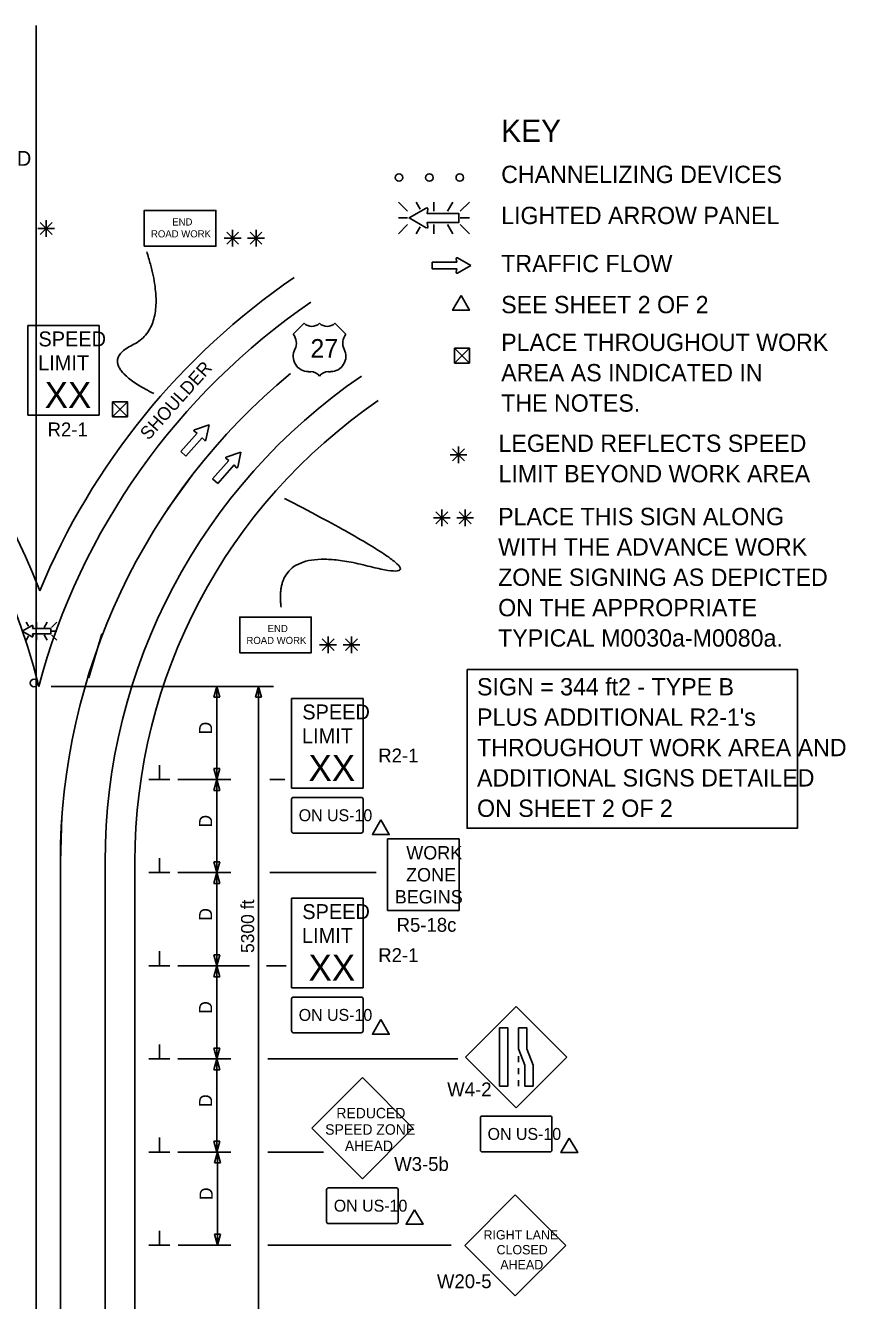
# Model space of a CAD drawing. Extents: x 16751 to 18479, y 5718 to 6974.
# Drawn here: x 16999 to 17439, y 6290 to 6974 of the extents above; entities that cross this region are included whole.
import ezdxf

# ---------------------------------------------------------------- set-up
doc = ezdxf.new("R2010")
doc.units = 0
for name, color, linetype in [('ALI_LEGAL_EX', 7, 'Continuous'), ('MT_SCRATCH_LEVEL_E', 7, 'Continuous'), ('PAVT_EDGE_EX', 7, 'Continuous'), ('TRAFFIC_SIGNS_PR', 7, 'Continuous'), ('TYPICAL_EX', 7, 'Continuous'), ('TYPICAL_TEXT_DIMEN_EX', 7, 'Continuous'), ('TYPICAL_TEXT_DIMEN_PR', 7, 'Continuous')]:
    doc.layers.add(name, color=color, linetype=linetype)

msp = doc.modelspace()

# ---------------------------------------------------------------- linework, layer by layer
at = {"layer": 'ALI_LEGAL_EX'}
for p, q in [((17004.68, 6974.12), (17004.68, 6155.98)), ((17004.68, 6877.04), (17004.68, 6013.12)), ((17039.84, 6647.53), (17032.85, 6623.88)), ((17017.65, 6024.8), (17017.65, 6525.15))]:
    msp.add_line(p, q, dxfattribs=at)
for points in [[(17004.68, 6949.12), (17004.68, 6974.12)], [(17075.14, 6714.42), (17089.89, 6734.61)], [(17017.7, 6524.8), (17017.65, 6525.15), (17018.48, 6549.78)], [(17017.65, 6424.8), (17017.65, 6449.8)], [(17017.7, 6324.8), (17017.7, 6349.8)]]:
    msp.add_lwpolyline(points, dxfattribs=at)
msp.add_arc((17357.65, 6525.15), 340, 129.56655, 180, dxfattribs=at)
at = {"layer": 'MT_SCRATCH_LEVEL_E'}
for p, q in [((17230.34, 6847.14), (17217.09, 6847.14)), ((17217.09, 6847.14), (17217.09, 6843.4)), ((17230.03, 6848.91), (17230.34, 6847.14)), ((17237.95, 6845.28), (17230.71, 6849.4)), ((17230.71, 6841.14), (17237.95, 6845.28)), ((17217.09, 6843.4), (17230.34, 6843.4)), ((17230.34, 6843.4), (17230.03, 6841.62)), ((17089.5, 6756.28), (17091.04, 6755.33)), ((17097.48, 6759.79), (17089.6, 6757.11)), ((17095.77, 6751.62), (17097.48, 6759.79)), ((17091.04, 6755.33), (17082.24, 6745.42)), ((17085.03, 6742.93), (17093.84, 6752.84)), ((17093.84, 6752.84), (17094.96, 6751.43)), ((17082.24, 6745.42), (17085.03, 6742.93)), ((17114.56, 6745.13), (17106.68, 6742.45)), ((17112.85, 6736.96), (17114.56, 6745.13)), ((17108.12, 6740.67), (17099.32, 6730.76)), ((17102.12, 6728.28), (17110.92, 6738.19)), ((17106.59, 6741.62), (17108.12, 6740.67)), ((17110.92, 6738.19), (17112.04, 6736.77)), ((17099.32, 6730.76), (17102.12, 6728.28))]:
    msp.add_line(p, q, dxfattribs=at)
for centre, start, end in [((17230.49, 6848.99), 60.42484, 189.96381), ((17230.49, 6841.55), 170.03619, 299.77312), ((17089.75, 6756.67), 108.80279, 238.34176), ((17095.31, 6751.73), 218.41415, 348.15107), ((17106.84, 6742.01), 108.80279, 238.34176), ((17112.4, 6737.07), 218.41415, 348.15107)]:
    msp.add_arc(centre, 0.463, start, end, dxfattribs=at)
at = {"layer": 'PAVT_EDGE_EX'}
for p, q in [((17041.65, 6525.15), (17041.65, 6186.91)), ((17057.65, 6525.15), (17057.65, 6186.91))]:
    msp.add_line(p, q, dxfattribs=at)
for centre, radius, start, end in [((16629.65, 6525.15), 404, 21.09612, 66.09058), ((16629.65, 6525.15), 388, 14.04823, 66.09058), ((17357.65, 6525.15), 380, 124.38118, 157.50106), ((17357.65, 6525.15), 364, 124.38118, 165.0045), ((17357.65, 6525.15), 316, 124.38117, 180), ((17357.65, 6525.15), 300, 124.38117, 180), ((17357.65, 6525.15), 300, 180, 180.00000277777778)]:
    msp.add_arc(centre, radius, start, end, dxfattribs=at)
at = {"layer": 'TRAFFIC_SIGNS_PR'}
for p, q in [((17199.02, 6879.29), (17203.95, 6874.36)), ((17210.78, 6875.47), (17208.57, 6879.3)), ((17218.1, 6874.36), (17218.1, 6879.3)), ((17225.34, 6874.36), (17228.19, 6879.3)), ((17232.25, 6874.36), (17237.19, 6879.3)), ((17203.95, 6870.8), (17199.02, 6870.8)), ((17199.02, 6862.32), (17203.95, 6867.25)), ((17208.53, 6862.31), (17210.64, 6865.98)), ((17218.1, 6867.25), (17218.1, 6862.31)), ((17228.23, 6862.31), (17225.38, 6867.25)), ((17232.25, 6870.8), (17237.19, 6870.8)), ((17232.25, 6867.25), (17237.19, 6862.31)), ((17000.14, 6813), (17038.54, 6813)), ((17000.14, 6765), (17000.14, 6813)), ((17038.54, 6765), (17038.54, 6813)), ((17000.14, 6765), (17038.54, 6765)), ((17000.64, 6651.64), (16999.38, 6653.82)), ((17004.82, 6651.01), (17004.82, 6653.82)), ((17008.96, 6651.01), (17010.59, 6653.82)), ((17012.91, 6651.01), (17015.73, 6653.83)), ((17004.82, 6646.94), (17004.82, 6644.12)), ((17010.61, 6644.12), (17008.98, 6646.94)), ((17012.91, 6648.97), (17015.73, 6648.97)), ((17012.91, 6646.94), (17015.73, 6644.12)), ((16999.35, 6644.12), (17000.56, 6646.21)), ((17141.7, 6612.74), (17180.1, 6612.74)), ((17141.7, 6564.74), (17141.7, 6612.74)), ((17180.1, 6564.74), (17180.1, 6612.74)), ((17141.7, 6564.74), (17180.1, 6564.74)), ((17141.7, 6558.74), (17141.7, 6541.54)), ((17142.7, 6559.74), (17179.1, 6559.74)), ((17180.1, 6558.74), (17180.1, 6541.54)), ((17142.7, 6540.54), (17179.1, 6540.54)), ((17193.28, 6499.02), (17193.28, 6537.42)), ((17193.28, 6537.42), (17231.68, 6537.42)), ((17231.68, 6499.02), (17231.68, 6537.42)), ((17141.7, 6505.55), (17180.1, 6505.55)), ((17141.7, 6457.55), (17141.7, 6505.55)), ((17180.1, 6457.55), (17180.1, 6505.55)), ((17193.28, 6499.02), (17231.68, 6499.02)), ((17141.7, 6457.55), (17180.1, 6457.55)), ((17141.7, 6451.55), (17141.7, 6434.35)), ((17142.7, 6452.55), (17179.1, 6452.55)), ((17180.1, 6451.55), (17180.1, 6434.35)), ((17262.25, 6447.4), (17235.1, 6420.25)), ((17289.4, 6420.25), (17262.25, 6447.4)), ((17142.7, 6433.35), (17179.1, 6433.35)), ((17263.49, 6420.74), (17263.49, 6417.54)), ((17235.1, 6420.25), (17262.25, 6393.1)), ((17262.25, 6393.1), (17289.4, 6420.25)), ((17263.49, 6414.34), (17263.49, 6411.14)), ((17179.71, 6409.29), (17152.55, 6382.13)), ((17206.86, 6382.13), (17179.71, 6409.29)), ((17263.49, 6407.94), (17263.49, 6404.74)), ((17243.05, 6387.65), (17243.05, 6370.45)), ((17244.05, 6388.65), (17280.45, 6388.65)), ((17281.45, 6387.65), (17281.45, 6370.45)), ((17152.55, 6382.13), (17179.71, 6354.98)), ((17179.71, 6354.98), (17206.86, 6382.13)), ((17244.05, 6369.45), (17280.45, 6369.45)), ((17160.53, 6349.13), (17160.53, 6331.93)), ((17161.53, 6350.13), (17197.93, 6350.13)), ((17198.93, 6349.13), (17198.93, 6331.93)), ((17261.76, 6346.39), (17234.61, 6319.24)), ((17288.91, 6319.24), (17261.76, 6346.39)), ((17161.53, 6330.93), (17197.93, 6330.93)), ((17234.61, 6319.24), (17261.76, 6292.09)), ((17261.76, 6292.09), (17288.91, 6319.24))]:
    msp.add_line(p, q, dxfattribs=at)
for points in [[(17062.69, 6855.62), (17101.09, 6855.62), (17101.09, 6874.82), (17062.69, 6874.82)], [(17113.9, 6637.34), (17152.3, 6637.34), (17152.3, 6656.54), (17113.9, 6656.54)], [(17253.36, 6435.99), (17253.36, 6404.74), (17257.85, 6404.74), (17257.85, 6435.99)], [(17263.49, 6435.99), (17263.49, 6424.8), (17266.84, 6415.92), (17266.84, 6404.74), (17271.33, 6404.74), (17271.33, 6415.92), (17267.99, 6424.8), (17267.99, 6435.99)]]:
    msp.add_lwpolyline(points, close=True, dxfattribs=at)
for points in [[(17214.03, 6876.08), (17204.74, 6870.8), (17214.03, 6865.48)], [(17214.9, 6866.11), (17214.5, 6868.38), (17231.52, 6868.38), (17231.52, 6873.18), (17214.5, 6873.18), (17214.91, 6875.46)], [(17002.5, 6651.99), (16997.19, 6648.97), (17002.5, 6645.93)], [(17003, 6646.29), (17002.77, 6647.59), (17012.49, 6647.59), (17012.49, 6650.33), (17002.77, 6650.33), (17003, 6651.63)]]:
    msp.add_lwpolyline(points, dxfattribs=at)
for centre in [(17199.36, 6892.49), (17215.66, 6892.49), (17231.96, 6892.49), (17003.5, 6621.15)]:
    msp.add_circle(centre, 2, dxfattribs=at)
for centre, radius, start, end in [((17214.32, 6875.56), 0.598, 350.73078, 118.89165), ((17214.32, 6866.01), 0.597, 241.48329, 9.95933), ((17002.66, 6651.69), 0.341, 350.73078, 118.89165), ((17002.66, 6646.23), 0.341, 241.48329, 9.95933), ((17142.7, 6558.74), 1, 90, 180), ((17179.1, 6558.74), 1, 0, 90), ((17142.7, 6541.54), 1, 180, 270), ((17179.1, 6541.54), 1, 270, 0), ((17142.7, 6451.55), 1, 90, 180), ((17179.1, 6451.55), 1, 0, 90), ((17142.7, 6434.35), 1, 180, 270), ((17179.1, 6434.35), 1, 270, 0), ((17244.05, 6387.65), 1, 90, 180), ((17280.45, 6387.65), 1, 0, 90), ((17244.05, 6370.45), 1, 180, 270), ((17280.45, 6370.45), 1, 270, 0), ((17161.53, 6349.13), 1, 90, 180), ((17197.93, 6349.13), 1, 0, 90), ((17161.53, 6331.93), 1, 180, 270), ((17197.93, 6331.93), 1, 270, 0)]:
    msp.add_arc(centre, radius, start, end, dxfattribs=at)
at = {"layer": 'TYPICAL_EX'}
for p, q in [((17142.58, 6808.34), (17148.47, 6814.24)), ((17170.88, 6808.34), (17164.98, 6814.24)), ((17150.83, 6788.28), (17152, 6788.28)), ((17162.63, 6788.28), (17161.45, 6788.28))]:
    msp.add_line(p, q, dxfattribs=at)
for centre, radius, start, end in [((17152.6, 6818.53), 5.96, 226.14041, 313.85958), ((17160.86, 6818.53), 5.96, 226.14042, 313.85959), ((17136.99, 6803.62), 7.31, 333.09768, 40.19361), ((17176.46, 6803.62), 7.31, 139.80639, 206.90233), ((17150.84, 6796.53), 8.24, 152.6698, 269.90132), ((17162.62, 6796.53), 8.24, 270.09868, 27.3302), ((17152.02, 6782.38), 5.91, 37.1038, 90.13853), ((17161.44, 6782.38), 5.91, 89.86147, 142.8962)]:
    msp.add_arc(centre, radius, start, end, dxfattribs=at)
at = {"layer": 'TYPICAL_TEXT_DIMEN_EX'}
msp.add_lwpolyline([(17235.92, 6628.43), (17413.13, 6628.43), (17413.13, 6543.16), (17235.92, 6543.16)], close=True, dxfattribs=at)
at = {"layer": 'TYPICAL_TEXT_DIMEN_PR'}
for p, q in [((17006.83, 6868.3), (17013.21, 6861.92)), ((17013.21, 6868.3), (17006.83, 6861.92)), ((17010.02, 6865.11), (17010.02, 6869.57)), ((17010.02, 6865.11), (17005.49, 6865.11)), ((17010.02, 6865.11), (17013.21, 6865.11)), ((17010.02, 6865.11), (17014.5, 6865.11)), ((17010.02, 6865.11), (17010.02, 6860.61)), ((17110.11, 6859.99), (17105.58, 6859.99)), ((17106.92, 6863.18), (17113.3, 6856.8)), ((17113.3, 6863.18), (17106.92, 6856.8)), ((17110.11, 6859.99), (17110.11, 6864.45)), ((17110.11, 6859.99), (17113.3, 6859.99)), ((17110.11, 6859.99), (17114.59, 6859.99)), ((17110.11, 6859.99), (17110.11, 6855.49)), ((17122.67, 6859.99), (17118.13, 6859.99)), ((17119.48, 6863.18), (17125.85, 6856.8)), ((17125.85, 6863.18), (17119.48, 6856.8)), ((17122.67, 6859.99), (17122.67, 6864.45)), ((17122.67, 6859.99), (17125.85, 6859.99)), ((17122.67, 6859.99), (17127.14, 6859.99)), ((17122.67, 6859.99), (17122.67, 6855.49)), ((17229.19, 6800.9), (17237.19, 6792.9)), ((17229.19, 6792.9), (17237.19, 6800.9)), ((17045.67, 6764.12), (17053.67, 6772.12)), ((17045.68, 6772.12), (17053.67, 6764.12)), ((17231.33, 6743.67), (17226.8, 6743.67)), ((17228.14, 6746.86), (17234.52, 6740.48)), ((17234.52, 6746.86), (17228.14, 6740.48)), ((17231.33, 6743.67), (17231.33, 6748.13)), ((17231.33, 6743.67), (17234.52, 6743.67)), ((17231.33, 6743.67), (17235.81, 6743.67)), ((17231.33, 6743.67), (17231.33, 6739.17)), ((17222.33, 6709.8), (17217.79, 6709.8)), ((17219.14, 6712.99), (17225.51, 6706.61)), ((17225.51, 6712.99), (17219.14, 6706.61)), ((17222.33, 6709.8), (17222.33, 6714.25)), ((17222.33, 6709.8), (17225.51, 6709.8)), ((17222.33, 6709.8), (17226.8, 6709.8)), ((17222.33, 6709.8), (17222.33, 6705.3)), ((17234.88, 6709.8), (17230.35, 6709.8)), ((17231.69, 6712.99), (17238.07, 6706.61)), ((17238.07, 6712.99), (17231.69, 6706.61)), ((17234.88, 6709.8), (17234.88, 6714.25)), ((17234.88, 6709.8), (17238.07, 6709.8)), ((17234.88, 6709.8), (17239.36, 6709.8)), ((17234.88, 6709.8), (17234.88, 6705.3)), ((17161.32, 6641.72), (17156.79, 6641.72)), ((17158.13, 6644.9), (17164.51, 6638.53)), ((17164.51, 6644.9), (17158.13, 6638.53)), ((17161.32, 6641.72), (17161.32, 6646.17)), ((17161.32, 6641.72), (17164.51, 6641.72)), ((17161.32, 6641.72), (17165.8, 6641.72)), ((17161.32, 6641.72), (17161.32, 6637.22)), ((17173.87, 6641.72), (17169.34, 6641.72)), ((17170.69, 6644.9), (17177.06, 6638.53)), ((17177.06, 6644.9), (17170.69, 6638.53)), ((17173.87, 6641.72), (17173.87, 6646.17)), ((17173.87, 6641.72), (17177.06, 6641.72)), ((17173.87, 6641.72), (17178.35, 6641.72)), ((17173.87, 6641.72), (17173.87, 6637.22)), ((17012.72, 6619.33), (17106.65, 6619.33)), ((17132.09, 6619.33), (17060.95, 6619.33)), ((17100.08, 6613.47), (17101.65, 6619.33)), ((17101.65, 6619.33), (17103.22, 6613.47)), ((17101.65, 6619.33), (17101.65, 6569.33)), ((17122.44, 6613.47), (17124.01, 6619.33)), ((17124.01, 6619.33), (17124.01, 6219.33)), ((17124.01, 6619.33), (17125.58, 6613.47)), ((17101.65, 6613.47), (17100.08, 6613.47)), ((17103.22, 6613.47), (17101.65, 6613.47)), ((17124.01, 6613.47), (17122.44, 6613.47)), ((17125.58, 6613.47), (17124.01, 6613.47)), ((17070.77, 6569.33), (17070.77, 6577.11)), ((17101.65, 6569.33), (17100.08, 6575.19)), ((17100.08, 6575.19), (17101.65, 6575.19)), ((17101.65, 6575.19), (17103.22, 6575.19)), ((17103.22, 6575.19), (17101.65, 6569.33)), ((17076.4, 6569.33), (17065.15, 6569.33)), ((17080.65, 6569.33), (17109.05, 6569.33)), ((17100.08, 6563.47), (17101.65, 6569.33)), ((17101.65, 6569.33), (17101.65, 6519.33)), ((17101.65, 6569.33), (17103.22, 6563.47)), ((17129.98, 6569.33), (17138.18, 6569.33)), ((17101.65, 6563.47), (17100.08, 6563.47)), ((17103.22, 6563.47), (17101.65, 6563.47)), ((17070.77, 6519.33), (17070.77, 6527.11)), ((17101.65, 6519.33), (17100.08, 6525.19)), ((17100.08, 6525.19), (17101.65, 6525.19)), ((17101.65, 6525.19), (17103.22, 6525.19)), ((17103.22, 6525.19), (17101.65, 6519.33)), ((17076.4, 6519.33), (17065.15, 6519.33)), ((17080.65, 6519.33), (17109.05, 6519.33)), ((17100.08, 6513.47), (17101.65, 6519.33)), ((17101.65, 6519.33), (17101.65, 6469.33)), ((17101.65, 6519.33), (17103.22, 6513.47)), ((17129.98, 6519.33), (17187.17, 6519.33)), ((17101.65, 6513.47), (17100.08, 6513.47)), ((17103.22, 6513.47), (17101.65, 6513.47)), ((17070.77, 6469.33), (17070.77, 6477.11)), ((17076.4, 6469.33), (17065.15, 6469.33)), ((17080.65, 6469.33), (17119.21, 6469.33)), ((17101.65, 6469.33), (17100.08, 6475.19)), ((17100.08, 6475.19), (17101.65, 6475.19)), ((17100.08, 6463.47), (17101.65, 6469.33)), ((17101.65, 6475.19), (17103.22, 6475.19)), ((17103.22, 6475.19), (17101.65, 6469.33)), ((17101.65, 6469.33), (17101.65, 6419.33)), ((17101.65, 6469.33), (17103.22, 6463.47)), ((17128.28, 6469.33), (17138.75, 6469.33)), ((17101.65, 6463.47), (17100.08, 6463.47)), ((17103.22, 6463.47), (17101.65, 6463.47)), ((17070.77, 6419.33), (17070.77, 6427.11)), ((17101.65, 6419.33), (17100.08, 6425.19)), ((17100.08, 6425.19), (17101.65, 6425.19)), ((17101.65, 6425.19), (17103.22, 6425.19)), ((17103.22, 6425.19), (17101.65, 6419.33)), ((17076.4, 6419.33), (17065.15, 6419.33)), ((17080.65, 6419.33), (17109.05, 6419.33)), ((17100.08, 6413.47), (17101.65, 6419.33)), ((17101.65, 6419.33), (17101.65, 6369.33)), ((17101.65, 6419.33), (17103.22, 6413.47)), ((17129, 6419.33), (17230.93, 6419.33)), ((17101.65, 6413.47), (17100.08, 6413.47)), ((17103.22, 6413.47), (17101.65, 6413.47)), ((17070.77, 6369.33), (17070.77, 6377.11)), ((17101.65, 6369.33), (17100.08, 6375.19)), ((17100.08, 6375.19), (17101.65, 6375.19)), ((17101.65, 6375.19), (17103.22, 6375.19)), ((17103.22, 6375.19), (17101.65, 6369.33)), ((17076.4, 6369.33), (17065.15, 6369.33)), ((17080.65, 6369.33), (17109.05, 6369.33)), ((17100.36, 6363.47), (17101.93, 6369.33)), ((17101.93, 6369.33), (17101.93, 6319.33)), ((17101.93, 6369.33), (17103.51, 6363.47)), ((17158.84, 6369.33), (17129, 6369.33)), ((17101.93, 6363.47), (17100.36, 6363.47)), ((17103.51, 6363.47), (17101.93, 6363.47)), ((17070.77, 6319.33), (17070.77, 6327.11)), ((17101.93, 6319.33), (17100.36, 6325.19)), ((17100.36, 6325.19), (17101.93, 6325.19)), ((17101.93, 6325.19), (17103.51, 6325.19)), ((17103.51, 6325.19), (17101.93, 6319.33)), ((17076.4, 6319.33), (17065.15, 6319.33)), ((17080.93, 6319.33), (17109.05, 6319.33)), ((17129, 6319.33), (17227.33, 6319.33))]:
    msp.add_line(p, q, dxfattribs=at)
for points in [[(17232.66, 6829.11), (17228.14, 6821.28), (17237.19, 6821.28)], [(17229.19, 6800.9), (17229.19, 6792.9), (17237.19, 6792.9), (17237.19, 6800.9)], [(17045.68, 6772.12), (17045.67, 6764.12), (17053.67, 6764.12), (17053.67, 6772.12)], [(17189.65, 6547.6), (17185.12, 6539.77), (17194.17, 6539.77)], [(17189.65, 6440.41), (17185.12, 6432.58), (17194.17, 6432.58)], [(17290.75, 6376.83), (17286.23, 6369), (17295.28, 6369)], [(17207.73, 6338.38), (17203.21, 6330.55), (17212.26, 6330.55)]]:
    msp.add_lwpolyline(points, close=True, dxfattribs=at)
for points in [[(17067.74, 6776.56), (17035.79, 6792.58), (17076.97, 6812.63), (17064.02, 6852.67)], [(17138.01, 6720.2), (17233.21, 6670.88), (17131.63, 6697.14), (17136.1, 6661.91)]]:
    msp.add_open_spline(points, degree=2, dxfattribs=at)

# ---------------------------------------------------------------- texts
at = {"layer": 'TRAFFIC_SIGNS_PR'}
for s, height, p in [('SPEED', 8, (16965.8, 6898.79)), ('END', 3.831, (17077.69, 6866.75)), ('ROAD WORK', 3.831, (17066.3, 6860.36)), ('SPEED', 8, (17005.91, 6801.86)), ('PLACE THROUGHOUT WORK', 9.3, (17254.2, 6799.39)), ('LIMIT', 8, (17005.75, 6789.06)), ('AREA AS INDICATED IN', 9.3, (17254.2, 6783.09)), ('XX', 14.031, (17009.25, 6768.76)), ('THE NOTES.', 9.3, (17254.2, 6766.79)), ('R2-1', 7.44, (17010.82, 6753.56)), ('PLACE THIS SIGN ALONG', 9.3, (17252.56, 6705.87)), ('WITH THE ADVANCE WORK', 9.3, (17252.56, 6689.57)), ('ZONE SIGNING AS DEPICTED', 9.3, (17252.56, 6673.27)), ('ON THE APPROPRIATE', 9.3, (17252.56, 6656.97)), ('END', 3.831, (17128.9, 6648.47)), ('TYPICAL M0030a-M0080a.', 9.3, (17252.56, 6640.67)), ('ROAD WORK', 3.831, (17117.5, 6642.09)), ('SPEED', 8, (17147.47, 6601.6)), ('LIMIT', 8, (17147.3, 6588.8)), ('R2-1', 7.44, (17188.24, 6578.52)), ('XX', 14.031, (17150.81, 6568.5)), ('ON US-10', 6.4, (17145.54, 6546.94)), ('WORK', 7.217, (17203.28, 6526.39)), ('ZONE', 7.217, (17203.16, 6514.58)), ('BEGINS', 7.217, (17197.09, 6502.77)), ('SPEED', 8, (17147.47, 6494.41)), ('LIMIT', 8, (17147.3, 6481.61)), ('R5-18c', 7.44, (17198.09, 6487.59)), ('XX', 14.031, (17150.81, 6461.31)), ('R2-1', 7.44, (17188.24, 6471.33)), ('ON US-10', 6.4, (17145.54, 6439.75)), ('W4-2', 7.441, (17225.25, 6399.24)), ('REDUCED', 5.6, (17165.76, 6387.44)), ('SPEED ZONE', 5.6, (17159.76, 6378.64)), ('ON US-10', 6.401, (17246.89, 6375.85)), ('AHEAD', 5.6, (17170.32, 6369.84)), ('W3-5b', 7.44, (17196.79, 6359.17)), ('ON US-10', 6.4, (17164.37, 6337.33)), ('RIGHT LANE', 4.999, (17244.71, 6322.39)), ('CLOSED', 4.999, (17251.69, 6314.39)), ('AHEAD', 4.999, (17253.74, 6306.4)), ('W20-5', 7.439, (17219.73, 6296.25))]:
    msp.add_text(s, height=height, dxfattribs=at).set_placement(p)
at = {"layer": 'TYPICAL_EX'}
msp.add_text('27', height=10, dxfattribs=at).set_placement((17151.84, 6795.77))
at = {"layer": 'TYPICAL_TEXT_DIMEN_EX'}
for s, height, p in [('KEY', 12, (17254.2, 6911.6)), ('CHANNELIZING DEVICES', 9.3, (17254.2, 6889.55)), ('LIGHTED ARROW PANEL', 9.3, (17254.2, 6867.5)), ('TRAFFIC FLOW', 9.3, (17254.2, 6841.7)), ('SEE SHEET 2 OF 2', 9.3, (17254.2, 6819.65)), ('LEGEND REFLECTS SPEED', 9.3, (17252.78, 6745.2)), ('LIMIT BEYOND WORK AREA', 9.3, (17252.78, 6728.9)), ('SIGN = 344 ft2 - TYPE B', 9.3, (17241.24, 6614.47)), ("PLUS ADDITIONAL R2-1's", 9.3, (17241.24, 6598.16)), ('THROUGHOUT WORK AREA AND', 9.3, (17241.24, 6581.86)), ('ADDITIONAL SIGNS DETAILED', 9.3, (17241.24, 6565.57)), ('ON SHEET 2 OF 2', 9.3, (17241.24, 6549.27))]:
    msp.add_text(s, height=height, dxfattribs=at).set_placement(p)
at = {"layer": 'TYPICAL_TEXT_DIMEN_PR'}
for s, rotation, p in [('SHOULDER', 48.37803, (17065, 6751.09)), ('D', 90, (17099.09, 6593.55)), ('D', 90, (17099.09, 6543.55)), ('5300 ft', 90, (17121.62, 6476.2)), ('D', 90, (17099.09, 6493.55)), ('D', 90, (17099.09, 6443.55)), ('D', 90, (17099.09, 6393.55)), ('D', 90, (17099.38, 6343.55))]:
    msp.add_text(s, height=7, rotation=rotation, dxfattribs=at).set_placement(p)

doc.saveas('drawing.dxf')
